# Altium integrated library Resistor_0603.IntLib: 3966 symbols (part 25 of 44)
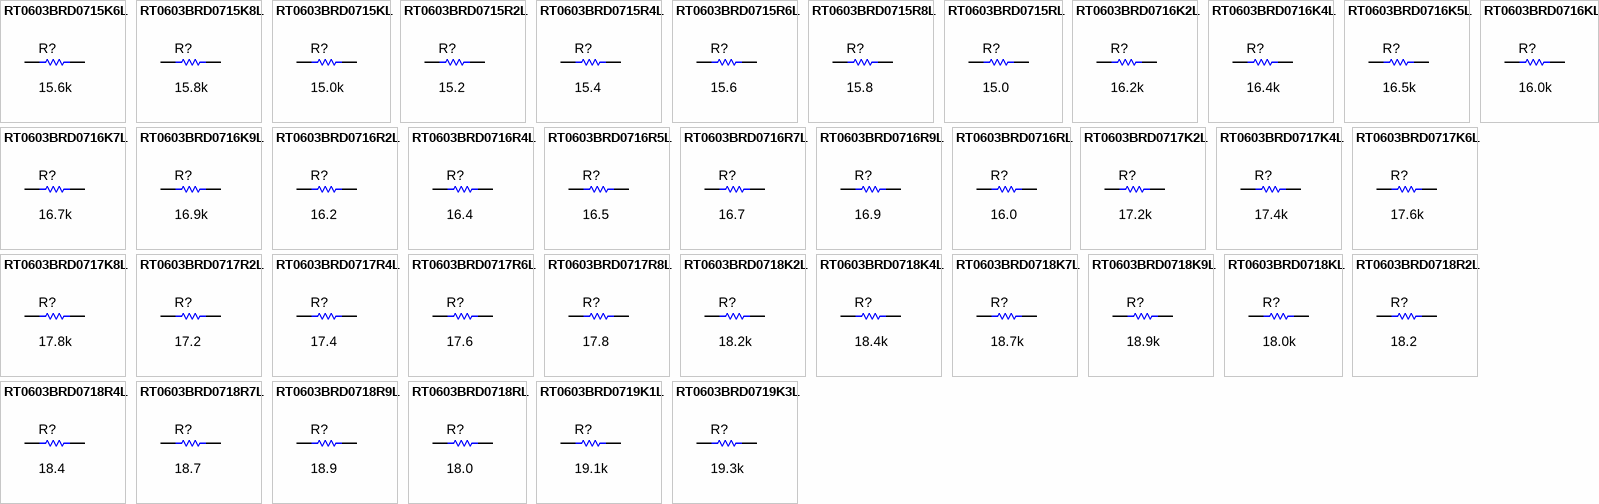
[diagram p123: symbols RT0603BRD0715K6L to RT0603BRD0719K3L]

## RT0603BRD0716KL
designator R?  ValueDisplayed: 16.0k  (hidden comment: RT0603BRD0716KL)
RES, 16.0 k, 0.1%, 0.1 W, 0603; Manufacturer: Yageo America; CompType: Resistor; Value: 16.0k; Res_ohm: 16000; Value_Code: 16k0; Tolerance_%: 0.1; Value2: 0.1W; VDC_V: 75; TempCo: 25 ppm/C; SizeArea_mm2: 1.28; SizeX_mm: 1.6; SizeY_mm: 0.8; SizeZ_mm: 1; EIA_Code: E192; U/M: EA; AEC Category: Q200
signal-integrity model Resistor
simulation model Resistor
footprint 0603
footprint 0603M
footprint 0603L
footprint 0603_HV
footprint 0603S
pins: 1, 2

## RT0603BRD0716R2L
designator R?  ValueDisplayed: 16.2  (hidden comment: RT0603BRD0716R2L)
RES, 16.2, 0.1%, 0.1 W, 0603; Manufacturer: Yageo America; CompType: Resistor; Value: 16.2; Value_Code: 16R2; Tolerance_%: 0.1; Value2: 0.1W; VDC_V: 75; TempCo: 25 ppm/C; SizeArea_mm2: 1.28; SizeX_mm: 1.6; SizeY_mm: 0.8; SizeZ_mm: 1; EIA_Code: E192; U/M: EA; AEC Category: Q200
signal-integrity model Resistor
simulation model Resistor
footprint 0603
footprint 0603M
footprint 0603L
footprint 0603_HV
footprint 0603S
pins: 1, 2

## RT0603BRD0716R4L
designator R?  ValueDisplayed: 16.4  (hidden comment: RT0603BRD0716R4L)
RES, 16.4, 0.1%, 0.1 W, 0603; Manufacturer: Yageo America; CompType: Resistor; Value: 16.4; Value_Code: 16R4; Tolerance_%: 0.1; Value2: 0.1W; VDC_V: 75; TempCo: 25 ppm/C; SizeArea_mm2: 1.28; SizeX_mm: 1.6; SizeY_mm: 0.8; SizeZ_mm: 1; EIA_Code: E192; U/M: EA; AEC Category: Q200
signal-integrity model Resistor
simulation model Resistor
footprint 0603
footprint 0603M
footprint 0603L
footprint 0603_HV
footprint 0603S
pins: 1, 2

## RT0603BRD0716R5L
designator R?  ValueDisplayed: 16.5  (hidden comment: RT0603BRD0716R5L)
RES, 16.5, 0.1%, 0.1 W, 0603; Manufacturer: Yageo America; CompType: Resistor; Value: 16.5; Value_Code: 16R5; Tolerance_%: 0.1; Value2: 0.1W; VDC_V: 75; TempCo: 25 ppm/C; SizeArea_mm2: 1.28; SizeX_mm: 1.6; SizeY_mm: 0.8; SizeZ_mm: 1; EIA_Code: E192; U/M: EA; AEC Category: Q200
signal-integrity model Resistor
simulation model Resistor
footprint 0603
footprint 0603M
footprint 0603L
footprint 0603_HV
footprint 0603S
pins: 1, 2

## RT0603BRD0716R7L
designator R?  ValueDisplayed: 16.7  (hidden comment: RT0603BRD0716R7L)
RES, 16.7, 0.1%, 0.1 W, 0603; Manufacturer: Yageo America; CompType: Resistor; Value: 16.7; Value_Code: 16R7; Tolerance_%: 0.1; Value2: 0.1W; VDC_V: 75; TempCo: 25 ppm/C; SizeArea_mm2: 1.28; SizeX_mm: 1.6; SizeY_mm: 0.8; SizeZ_mm: 1; EIA_Code: E192; U/M: EA; AEC Category: Q200
signal-integrity model Resistor
simulation model Resistor
footprint 0603
footprint 0603M
footprint 0603L
footprint 0603_HV
footprint 0603S
pins: 1, 2

## RT0603BRD0716R9L
designator R?  ValueDisplayed: 16.9  (hidden comment: RT0603BRD0716R9L)
RES, 16.9, 0.1%, 0.1 W, 0603; Manufacturer: Yageo America; CompType: Resistor; Value: 16.9; Value_Code: 16R9; Tolerance_%: 0.1; Value2: 0.1W; VDC_V: 75; TempCo: 25 ppm/C; SizeArea_mm2: 1.28; SizeX_mm: 1.6; SizeY_mm: 0.8; SizeZ_mm: 1; EIA_Code: E192; U/M: EA; AEC Category: Q200
signal-integrity model Resistor
simulation model Resistor
footprint 0603
footprint 0603M
footprint 0603L
footprint 0603_HV
footprint 0603S
pins: 1, 2

## RT0603BRD0716RL
designator R?  ValueDisplayed: 16.0  (hidden comment: RT0603BRD0716RL)
RES, 16.0, 0.1%, 0.1 W, 0603; Manufacturer: Yageo America; CompType: Resistor; Value: 16.0; Res_ohm: 16; Value_Code: 16R0; Tolerance_%: 0.1; Value2: 0.1W; VDC_V: 75; TempCo: 25 ppm/C; SizeArea_mm2: 1.28; SizeX_mm: 1.6; SizeY_mm: 0.8; SizeZ_mm: 1; EIA_Code: E192; U/M: EA; AEC Category: Q200
signal-integrity model Resistor
simulation model Resistor
footprint 0603
footprint 0603M
footprint 0603L
footprint 0603_HV
footprint 0603S
pins: 1, 2

## RT0603BRD0717K2L
designator R?  ValueDisplayed: 17.2k  (hidden comment: RT0603BRD0717K2L)
RES, 17.2 k, 0.1%, 0.1 W, 0603; Manufacturer: Yageo America; CompType: Resistor; Value: 17.2k; Res_ohm: 17200; Value_Code: 17k2; Tolerance_%: 0.1; Value2: 0.1W; VDC_V: 75; TempCo: 25 ppm/C; SizeArea_mm2: 1.28; SizeX_mm: 1.6; SizeY_mm: 0.8; SizeZ_mm: 1; EIA_Code: E192; U/M: EA; AEC Category: Q200
signal-integrity model Resistor
simulation model Resistor
footprint 0603
footprint 0603M
footprint 0603L
footprint 0603_HV
footprint 0603S
pins: 1, 2

## RT0603BRD0717K4L
designator R?  ValueDisplayed: 17.4k  (hidden comment: RT0603BRD0717K4L)
RES, 17.4 k, 0.1%, 0.1 W, 0603; Manufacturer: Yageo America; CompType: Resistor; Value: 17.4k; Res_ohm: 17400; Value_Code: 17k4; Tolerance_%: 0.1; Value2: 0.1W; VDC_V: 75; TempCo: 25 ppm/C; SizeArea_mm2: 1.28; SizeX_mm: 1.6; SizeY_mm: 0.8; SizeZ_mm: 1; EIA_Code: E192; U/M: EA; AEC Category: Q200
signal-integrity model Resistor
simulation model Resistor
footprint 0603
footprint 0603M
footprint 0603L
footprint 0603_HV
footprint 0603S
pins: 1, 2

## RT0603BRD0717K6L
designator R?  ValueDisplayed: 17.6k  (hidden comment: RT0603BRD0717K6L)
RES, 17.6 k, 0.1%, 0.1 W, 0603; Manufacturer: Yageo America; CompType: Resistor; Value: 17.6k; Res_ohm: 17600; Value_Code: 17k6; Tolerance_%: 0.1; Value2: 0.1W; VDC_V: 75; TempCo: 25 ppm/C; SizeArea_mm2: 1.28; SizeX_mm: 1.6; SizeY_mm: 0.8; SizeZ_mm: 1; EIA_Code: E192; U/M: EA; AEC Category: Q200
signal-integrity model Resistor
simulation model Resistor
footprint 0603
footprint 0603M
footprint 0603L
footprint 0603_HV
footprint 0603S
pins: 1, 2

## RT0603BRD0717K8L
designator R?  ValueDisplayed: 17.8k  (hidden comment: RT0603BRD0717K8L)
RES, 17.8 k, 0.1%, 0.1 W, 0603; Manufacturer: Yageo America; CompType: Resistor; Value: 17.8k; Res_ohm: 17800; Value_Code: 17k8; Tolerance_%: 0.1; Value2: 0.1W; VDC_V: 75; TempCo: 25 ppm/C; SizeArea_mm2: 1.28; SizeX_mm: 1.6; SizeY_mm: 0.8; SizeZ_mm: 1; EIA_Code: E192; U/M: EA; AEC Category: Q200
signal-integrity model Resistor
simulation model Resistor
footprint 0603
footprint 0603M
footprint 0603L
footprint 0603_HV
footprint 0603S
pins: 1, 2

## RT0603BRD0717R2L
designator R?  ValueDisplayed: 17.2  (hidden comment: RT0603BRD0717R2L)
RES, 17.2, 0.1%, 0.1 W, 0603; Manufacturer: Yageo America; CompType: Resistor; Value: 17.2; Value_Code: 17R2; Tolerance_%: 0.1; Value2: 0.1W; VDC_V: 75; TempCo: 25 ppm/C; SizeArea_mm2: 1.28; SizeX_mm: 1.6; SizeY_mm: 0.8; SizeZ_mm: 1; EIA_Code: E192; U/M: EA; AEC Category: Q200
signal-integrity model Resistor
simulation model Resistor
footprint 0603
footprint 0603M
footprint 0603L
footprint 0603_HV
footprint 0603S
pins: 1, 2

## RT0603BRD0717R4L
designator R?  ValueDisplayed: 17.4  (hidden comment: RT0603BRD0717R4L)
RES, 17.4, 0.1%, 0.1 W, 0603; Manufacturer: Yageo America; CompType: Resistor; Value: 17.4; Value_Code: 17R4; Tolerance_%: 0.1; Value2: 0.1W; VDC_V: 75; TempCo: 25 ppm/C; SizeArea_mm2: 1.28; SizeX_mm: 1.6; SizeY_mm: 0.8; SizeZ_mm: 1; EIA_Code: E192; U/M: EA; AEC Category: Q200
signal-integrity model Resistor
simulation model Resistor
footprint 0603
footprint 0603M
footprint 0603L
footprint 0603_HV
footprint 0603S
pins: 1, 2

## RT0603BRD0717R6L
designator R?  ValueDisplayed: 17.6  (hidden comment: RT0603BRD0717R6L)
RES, 17.6, 0.1%, 0.1 W, 0603; Manufacturer: Yageo America; CompType: Resistor; Value: 17.6; Value_Code: 17R6; Tolerance_%: 0.1; Value2: 0.1W; VDC_V: 75; TempCo: 25 ppm/C; SizeArea_mm2: 1.28; SizeX_mm: 1.6; SizeY_mm: 0.8; SizeZ_mm: 1; EIA_Code: E192; U/M: EA; AEC Category: Q200
signal-integrity model Resistor
simulation model Resistor
footprint 0603
footprint 0603M
footprint 0603L
footprint 0603_HV
footprint 0603S
pins: 1, 2

## RT0603BRD0717R8L
designator R?  ValueDisplayed: 17.8  (hidden comment: RT0603BRD0717R8L)
RES, 17.8, 0.1%, 0.1 W, 0603; Manufacturer: Yageo America; CompType: Resistor; Value: 17.8; Value_Code: 17R8; Tolerance_%: 0.1; Value2: 0.1W; VDC_V: 75; TempCo: 25 ppm/C; SizeArea_mm2: 1.28; SizeX_mm: 1.6; SizeY_mm: 0.8; SizeZ_mm: 1; EIA_Code: E192; U/M: EA; AEC Category: Q200
signal-integrity model Resistor
simulation model Resistor
footprint 0603
footprint 0603M
footprint 0603L
footprint 0603_HV
footprint 0603S
pins: 1, 2

## RT0603BRD0718K2L
designator R?  ValueDisplayed: 18.2k  (hidden comment: RT0603BRD0718K2L)
RES, 18.2 k, 0.1%, 0.1 W, 0603; Manufacturer: Yageo America; CompType: Resistor; Value: 18.2k; Res_ohm: 18200; Value_Code: 18k2; Tolerance_%: 0.1; Value2: 0.1W; VDC_V: 75; TempCo: 25 ppm/C; SizeArea_mm2: 1.28; SizeX_mm: 1.6; SizeY_mm: 0.8; SizeZ_mm: 1; EIA_Code: E192; U/M: EA; AEC Category: Q200
signal-integrity model Resistor
simulation model Resistor
footprint 0603
footprint 0603M
footprint 0603L
footprint 0603_HV
footprint 0603S
pins: 1, 2

## RT0603BRD0718K4L
designator R?  ValueDisplayed: 18.4k  (hidden comment: RT0603BRD0718K4L)
RES, 18.4 k, 0.1%, 0.1 W, 0603; Manufacturer: Yageo America; CompType: Resistor; Value: 18.4k; Res_ohm: 18400; Value_Code: 18k4; Tolerance_%: 0.1; Value2: 0.1W; VDC_V: 75; TempCo: 25 ppm/C; SizeArea_mm2: 1.28; SizeX_mm: 1.6; SizeY_mm: 0.8; SizeZ_mm: 1; EIA_Code: E192; U/M: EA; AEC Category: Q200
signal-integrity model Resistor
simulation model Resistor
footprint 0603
footprint 0603M
footprint 0603L
footprint 0603_HV
footprint 0603S
pins: 1, 2

## RT0603BRD0718K7L
designator R?  ValueDisplayed: 18.7k  (hidden comment: RT0603BRD0718K7L)
RES, 18.7 k, 0.1%, 0.1 W, 0603; Manufacturer: Yageo America; CompType: Resistor; Value: 18.7k; Res_ohm: 18700; Value_Code: 18k7; Tolerance_%: 0.1; Value2: 0.1W; VDC_V: 75; TempCo: 25 ppm/C; SizeArea_mm2: 1.28; SizeX_mm: 1.6; SizeY_mm: 0.8; SizeZ_mm: 1; EIA_Code: E192; U/M: EA; AEC Category: Q200
signal-integrity model Resistor
simulation model Resistor
footprint 0603
footprint 0603M
footprint 0603L
footprint 0603_HV
footprint 0603S
pins: 1, 2

## RT0603BRD0718K9L
designator R?  ValueDisplayed: 18.9k  (hidden comment: RT0603BRD0718K9L)
RES, 18.9 k, 0.1%, 0.1 W, 0603; Manufacturer: Yageo America; CompType: Resistor; Value: 18.9k; Res_ohm: 18900; Value_Code: 18k9; Tolerance_%: 0.1; Value2: 0.1W; VDC_V: 75; TempCo: 25 ppm/C; SizeArea_mm2: 1.28; SizeX_mm: 1.6; SizeY_mm: 0.8; SizeZ_mm: 1; EIA_Code: E192; U/M: EA; AEC Category: Q200
signal-integrity model Resistor
simulation model Resistor
footprint 0603
footprint 0603M
footprint 0603L
footprint 0603_HV
footprint 0603S
pins: 1, 2

## RT0603BRD0718KL
designator R?  ValueDisplayed: 18.0k  (hidden comment: RT0603BRD0718KL)
RES, 18.0 k, 0.1%, 0.1 W, 0603; Manufacturer: Yageo America; CompType: Resistor; Value: 18.0k; Res_ohm: 18000; Value_Code: 18k0; Tolerance_%: 0.1; Value2: 0.1W; VDC_V: 75; TempCo: 25 ppm/C; SizeArea_mm2: 1.28; SizeX_mm: 1.6; SizeY_mm: 0.8; SizeZ_mm: 1; EIA_Code: E192; U/M: EA; AEC Category: Q200
signal-integrity model Resistor
simulation model Resistor
footprint 0603
footprint 0603M
footprint 0603L
footprint 0603_HV
footprint 0603S
pins: 1, 2

## RT0603BRD0718R2L
designator R?  ValueDisplayed: 18.2  (hidden comment: RT0603BRD0718R2L)
RES, 18.2, 0.1%, 0.1 W, 0603; Manufacturer: Yageo America; CompType: Resistor; Value: 18.2; Value_Code: 18R2; Tolerance_%: 0.1; Value2: 0.1W; VDC_V: 75; TempCo: 25 ppm/C; SizeArea_mm2: 1.28; SizeX_mm: 1.6; SizeY_mm: 0.8; SizeZ_mm: 1; EIA_Code: E192; U/M: EA; AEC Category: Q200
signal-integrity model Resistor
simulation model Resistor
footprint 0603
footprint 0603M
footprint 0603L
footprint 0603_HV
footprint 0603S
pins: 1, 2

## RT0603BRD0718R4L
designator R?  ValueDisplayed: 18.4  (hidden comment: RT0603BRD0718R4L)
RES, 18.4, 0.1%, 0.1 W, 0603; Manufacturer: Yageo America; CompType: Resistor; Value: 18.4; Value_Code: 18R4; Tolerance_%: 0.1; Value2: 0.1W; VDC_V: 75; TempCo: 25 ppm/C; SizeArea_mm2: 1.28; SizeX_mm: 1.6; SizeY_mm: 0.8; SizeZ_mm: 1; EIA_Code: E192; U/M: EA; AEC Category: Q200
signal-integrity model Resistor
simulation model Resistor
footprint 0603
footprint 0603M
footprint 0603L
footprint 0603_HV
footprint 0603S
pins: 1, 2

## RT0603BRD0718R7L
designator R?  ValueDisplayed: 18.7  (hidden comment: RT0603BRD0718R7L)
RES, 18.7, 0.1%, 0.1 W, 0603; Manufacturer: Yageo America; CompType: Resistor; Value: 18.7; Value_Code: 18R7; Tolerance_%: 0.1; Value2: 0.1W; VDC_V: 75; TempCo: 25 ppm/C; SizeArea_mm2: 1.28; SizeX_mm: 1.6; SizeY_mm: 0.8; SizeZ_mm: 1; EIA_Code: E192; U/M: EA; AEC Category: Q200
signal-integrity model Resistor
simulation model Resistor
footprint 0603
footprint 0603M
footprint 0603L
footprint 0603_HV
footprint 0603S
pins: 1, 2

## RT0603BRD0718R9L
designator R?  ValueDisplayed: 18.9  (hidden comment: RT0603BRD0718R9L)
RES, 18.9, 0.1%, 0.1 W, 0603; Manufacturer: Yageo America; CompType: Resistor; Value: 18.9; Value_Code: 18R9; Tolerance_%: 0.1; Value2: 0.1W; VDC_V: 75; TempCo: 25 ppm/C; SizeArea_mm2: 1.28; SizeX_mm: 1.6; SizeY_mm: 0.8; SizeZ_mm: 1; EIA_Code: E192; U/M: EA; AEC Category: Q200
signal-integrity model Resistor
simulation model Resistor
footprint 0603
footprint 0603M
footprint 0603L
footprint 0603_HV
footprint 0603S
pins: 1, 2

## RT0603BRD0718RL
designator R?  ValueDisplayed: 18.0  (hidden comment: RT0603BRD0718RL)
RES, 18.0, 0.1%, 0.1 W, 0603; Manufacturer: Yageo America; CompType: Resistor; Value: 18.0; Res_ohm: 18; Value_Code: 18R0; Tolerance_%: 0.1; Value2: 0.1W; VDC_V: 75; TempCo: 25 ppm/C; SizeArea_mm2: 1.28; SizeX_mm: 1.6; SizeY_mm: 0.8; SizeZ_mm: 1; EIA_Code: E192; U/M: EA; AEC Category: Q200
signal-integrity model Resistor
simulation model Resistor
footprint 0603
footprint 0603M
footprint 0603L
footprint 0603_HV
footprint 0603S
pins: 1, 2

## RT0603BRD0719K1L
designator R?  ValueDisplayed: 19.1k  (hidden comment: RT0603BRD0719K1L)
RES, 19.1 k, 0.1%, 0.1 W, 0603; Manufacturer: Yageo America; CompType: Resistor; Value: 19.1k; Res_ohm: 19100; Value_Code: 19k1; Tolerance_%: 0.1; Value2: 0.1W; VDC_V: 75; TempCo: 25 ppm/C; SizeArea_mm2: 1.28; SizeX_mm: 1.6; SizeY_mm: 0.8; SizeZ_mm: 1; EIA_Code: E192; U/M: EA; AEC Category: Q200
signal-integrity model Resistor
simulation model Resistor
footprint 0603
footprint 0603M
footprint 0603L
footprint 0603_HV
footprint 0603S
pins: 1, 2

## RT0603BRD0719K3L
designator R?  ValueDisplayed: 19.3k  (hidden comment: RT0603BRD0719K3L)
RES, 19.3 k, 0.1%, 0.1 W, 0603; Manufacturer: Yageo America; CompType: Resistor; Value: 19.3k; Res_ohm: 19300; Value_Code: 19k3; Tolerance_%: 0.1; Value2: 0.1W; VDC_V: 75; TempCo: 25 ppm/C; SizeArea_mm2: 1.28; SizeX_mm: 1.6; SizeY_mm: 0.8; SizeZ_mm: 1; EIA_Code: E192; U/M: EA; AEC Category: Q200
signal-integrity model Resistor
simulation model Resistor
footprint 0603
footprint 0603M
footprint 0603L
footprint 0603_HV
footprint 0603S
pins: 1, 2

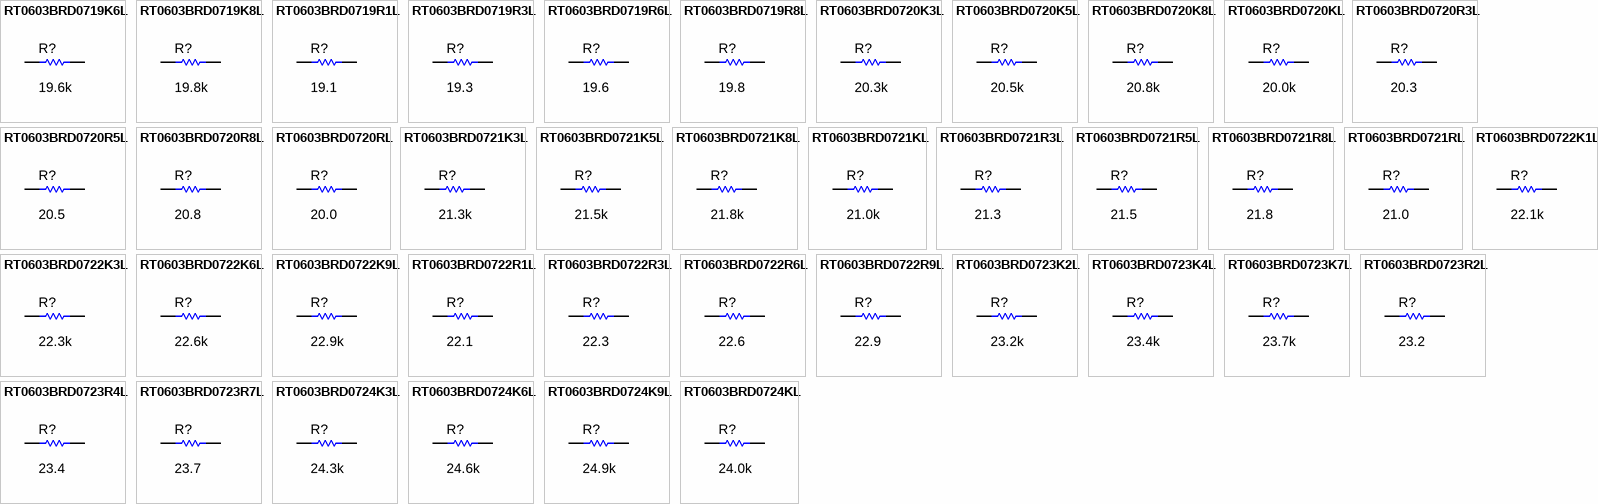
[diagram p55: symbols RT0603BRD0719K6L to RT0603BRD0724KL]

## RT0603BRD0719K6L
designator R?  ValueDisplayed: 19.6k  (hidden comment: RT0603BRD0719K6L)
RES, 19.6 k, 0.1%, 0.1 W, 0603; Manufacturer: Yageo America; CompType: Resistor; Value: 19.6k; Res_ohm: 19600; Value_Code: 19k6; Tolerance_%: 0.1; Value2: 0.1W; VDC_V: 75; TempCo: 25 ppm/C; SizeArea_mm2: 1.28; SizeX_mm: 1.6; SizeY_mm: 0.8; SizeZ_mm: 1; EIA_Code: E192; U/M: EA; AEC Category: Q200
signal-integrity model Resistor
simulation model Resistor
footprint 0603
footprint 0603M
footprint 0603L
footprint 0603_HV
footprint 0603S
pins: 1, 2

## RT0603BRD0719K8L
designator R?  ValueDisplayed: 19.8k  (hidden comment: RT0603BRD0719K8L)
RES, 19.8 k, 0.1%, 0.1 W, 0603; Manufacturer: Yageo America; CompType: Resistor; Value: 19.8k; Res_ohm: 19800; Value_Code: 19k8; Tolerance_%: 0.1; Value2: 0.1W; VDC_V: 75; TempCo: 25 ppm/C; SizeArea_mm2: 1.28; SizeX_mm: 1.6; SizeY_mm: 0.8; SizeZ_mm: 1; EIA_Code: E192; U/M: EA; AEC Category: Q200
signal-integrity model Resistor
simulation model Resistor
footprint 0603
footprint 0603M
footprint 0603L
footprint 0603_HV
footprint 0603S
pins: 1, 2

## RT0603BRD0719R1L
designator R?  ValueDisplayed: 19.1  (hidden comment: RT0603BRD0719R1L)
RES, 19.1, 0.1%, 0.1 W, 0603; Manufacturer: Yageo America; CompType: Resistor; Value: 19.1; Value_Code: 19R1; Tolerance_%: 0.1; Value2: 0.1W; VDC_V: 75; TempCo: 25 ppm/C; SizeArea_mm2: 1.28; SizeX_mm: 1.6; SizeY_mm: 0.8; SizeZ_mm: 1; EIA_Code: E192; U/M: EA; AEC Category: Q200
signal-integrity model Resistor
simulation model Resistor
footprint 0603
footprint 0603M
footprint 0603L
footprint 0603_HV
footprint 0603S
pins: 1, 2

## RT0603BRD0719R3L
designator R?  ValueDisplayed: 19.3  (hidden comment: RT0603BRD0719R3L)
RES, 19.3, 0.1%, 0.1 W, 0603; Manufacturer: Yageo America; CompType: Resistor; Value: 19.3; Value_Code: 19R3; Tolerance_%: 0.1; Value2: 0.1W; VDC_V: 75; TempCo: 25 ppm/C; SizeArea_mm2: 1.28; SizeX_mm: 1.6; SizeY_mm: 0.8; SizeZ_mm: 1; EIA_Code: E192; U/M: EA; AEC Category: Q200
signal-integrity model Resistor
simulation model Resistor
footprint 0603
footprint 0603M
footprint 0603L
footprint 0603_HV
footprint 0603S
pins: 1, 2

## RT0603BRD0719R6L
designator R?  ValueDisplayed: 19.6  (hidden comment: RT0603BRD0719R6L)
RES, 19.6, 0.1%, 0.1 W, 0603; Manufacturer: Yageo America; CompType: Resistor; Value: 19.6; Value_Code: 19R6; Tolerance_%: 0.1; Value2: 0.1W; VDC_V: 75; TempCo: 25 ppm/C; SizeArea_mm2: 1.28; SizeX_mm: 1.6; SizeY_mm: 0.8; SizeZ_mm: 1; EIA_Code: E192; U/M: EA; AEC Category: Q200
signal-integrity model Resistor
simulation model Resistor
footprint 0603
footprint 0603M
footprint 0603L
footprint 0603_HV
footprint 0603S
pins: 1, 2

## RT0603BRD0719R8L
designator R?  ValueDisplayed: 19.8  (hidden comment: RT0603BRD0719R8L)
RES, 19.8, 0.1%, 0.1 W, 0603; Manufacturer: Yageo America; CompType: Resistor; Value: 19.8; Value_Code: 19R8; Tolerance_%: 0.1; Value2: 0.1W; VDC_V: 75; TempCo: 25 ppm/C; SizeArea_mm2: 1.28; SizeX_mm: 1.6; SizeY_mm: 0.8; SizeZ_mm: 1; EIA_Code: E192; U/M: EA; AEC Category: Q200
signal-integrity model Resistor
simulation model Resistor
footprint 0603
footprint 0603M
footprint 0603L
footprint 0603_HV
footprint 0603S
pins: 1, 2

## RT0603BRD0720K3L
designator R?  ValueDisplayed: 20.3k  (hidden comment: RT0603BRD0720K3L)
RES, 20.3 k, 0.1%, 0.1 W, 0603; Manufacturer: Yageo America; CompType: Resistor; Value: 20.3k; Res_ohm: 20300; Value_Code: 20k3; Tolerance_%: 0.1; Value2: 0.1W; VDC_V: 75; TempCo: 25 ppm/C; SizeArea_mm2: 1.28; SizeX_mm: 1.6; SizeY_mm: 0.8; SizeZ_mm: 1; EIA_Code: E192; U/M: EA; AEC Category: Q200
signal-integrity model Resistor
simulation model Resistor
footprint 0603
footprint 0603M
footprint 0603L
footprint 0603_HV
footprint 0603S
pins: 1, 2

## RT0603BRD0720K5L
designator R?  ValueDisplayed: 20.5k  (hidden comment: RT0603BRD0720K5L)
RES, 20.5 k, 0.1%, 0.1 W, 0603; Manufacturer: Yageo America; CompType: Resistor; Value: 20.5k; Res_ohm: 20500; Value_Code: 20k5; Tolerance_%: 0.1; Value2: 0.1W; VDC_V: 75; TempCo: 25 ppm/C; SizeArea_mm2: 1.28; SizeX_mm: 1.6; SizeY_mm: 0.8; SizeZ_mm: 1; EIA_Code: E192; U/M: EA; AEC Category: Q200
signal-integrity model Resistor
simulation model Resistor
footprint 0603
footprint 0603M
footprint 0603L
footprint 0603_HV
footprint 0603S
pins: 1, 2

## RT0603BRD0720K8L
designator R?  ValueDisplayed: 20.8k  (hidden comment: RT0603BRD0720K8L)
RES, 20.8 k, 0.1%, 0.1 W, 0603; Manufacturer: Yageo America; CompType: Resistor; Value: 20.8k; Res_ohm: 20800; Value_Code: 20k8; Tolerance_%: 0.1; Value2: 0.1W; VDC_V: 75; TempCo: 25 ppm/C; SizeArea_mm2: 1.28; SizeX_mm: 1.6; SizeY_mm: 0.8; SizeZ_mm: 1; EIA_Code: E192; U/M: EA; AEC Category: Q200
signal-integrity model Resistor
simulation model Resistor
footprint 0603
footprint 0603M
footprint 0603L
footprint 0603_HV
footprint 0603S
pins: 1, 2

## RT0603BRD0720KL
designator R?  ValueDisplayed: 20.0k  (hidden comment: RT0603BRD0720KL)
RES, 20.0 k, 0.1%, 0.1 W, 0603; Manufacturer: Yageo America; CompType: Resistor; Value: 20.0k; Res_ohm: 20000; Value_Code: 20k0; Tolerance_%: 0.1; Value2: 0.1W; VDC_V: 75; TempCo: 25 ppm/C; SizeArea_mm2: 1.28; SizeX_mm: 1.6; SizeY_mm: 0.8; SizeZ_mm: 1; EIA_Code: E192; U/M: EA; AEC Category: Q200; Green_Lifecycle: Active; Green_REACh: Passed
signal-integrity model Resistor
simulation model Resistor
footprint 0603
footprint 0603M
footprint 0603L
footprint 0603_HV
footprint 0603S
pins: 1, 2

## RT0603BRD0720R3L
designator R?  ValueDisplayed: 20.3  (hidden comment: RT0603BRD0720R3L)
RES, 20.3, 0.1%, 0.1 W, 0603; Manufacturer: Yageo America; CompType: Resistor; Value: 20.3; Value_Code: 20R3; Tolerance_%: 0.1; Value2: 0.1W; VDC_V: 75; TempCo: 25 ppm/C; SizeArea_mm2: 1.28; SizeX_mm: 1.6; SizeY_mm: 0.8; SizeZ_mm: 1; EIA_Code: E192; U/M: EA; AEC Category: Q200
signal-integrity model Resistor
simulation model Resistor
footprint 0603
footprint 0603M
footprint 0603L
footprint 0603_HV
footprint 0603S
pins: 1, 2

## RT0603BRD0720R5L
designator R?  ValueDisplayed: 20.5  (hidden comment: RT0603BRD0720R5L)
RES, 20.5, 0.1%, 0.1 W, 0603; Manufacturer: Yageo America; CompType: Resistor; Value: 20.5; Value_Code: 20R5; Tolerance_%: 0.1; Value2: 0.1W; VDC_V: 75; TempCo: 25 ppm/C; SizeArea_mm2: 1.28; SizeX_mm: 1.6; SizeY_mm: 0.8; SizeZ_mm: 1; EIA_Code: E192; U/M: EA; AEC Category: Q200
signal-integrity model Resistor
simulation model Resistor
footprint 0603
footprint 0603M
footprint 0603L
footprint 0603_HV
footprint 0603S
pins: 1, 2

## RT0603BRD0720R8L
designator R?  ValueDisplayed: 20.8  (hidden comment: RT0603BRD0720R8L)
RES, 20.8, 0.1%, 0.1 W, 0603; Manufacturer: Yageo America; CompType: Resistor; Value: 20.8; Value_Code: 20R8; Tolerance_%: 0.1; Value2: 0.1W; VDC_V: 75; TempCo: 25 ppm/C; SizeArea_mm2: 1.28; SizeX_mm: 1.6; SizeY_mm: 0.8; SizeZ_mm: 1; EIA_Code: E192; U/M: EA; AEC Category: Q200
signal-integrity model Resistor
simulation model Resistor
footprint 0603
footprint 0603M
footprint 0603L
footprint 0603_HV
footprint 0603S
pins: 1, 2

## RT0603BRD0720RL
designator R?  ValueDisplayed: 20.0  (hidden comment: RT0603BRD0720RL)
RES, 20.0, 0.1%, 0.1 W, 0603; Manufacturer: Yageo America; CompType: Resistor; Value: 20.0; Res_ohm: 20; Value_Code: 20R0; Tolerance_%: 0.1; Value2: 0.1W; VDC_V: 75; TempCo: 25 ppm/C; SizeArea_mm2: 1.28; SizeX_mm: 1.6; SizeY_mm: 0.8; SizeZ_mm: 1; EIA_Code: E192; U/M: EA; AEC Category: Q200; Green_Lifecycle: Active; Green_REACh: Passed
signal-integrity model Resistor
simulation model Resistor
footprint 0603
footprint 0603M
footprint 0603L
footprint 0603_HV
footprint 0603S
pins: 1, 2

## RT0603BRD0721K3L
designator R?  ValueDisplayed: 21.3k  (hidden comment: RT0603BRD0721K3L)
RES, 21.3 k, 0.1%, 0.1 W, 0603; Manufacturer: Yageo America; CompType: Resistor; Value: 21.3k; Res_ohm: 21300; Value_Code: 21k3; Tolerance_%: 0.1; Value2: 0.1W; VDC_V: 75; TempCo: 25 ppm/C; SizeArea_mm2: 1.28; SizeX_mm: 1.6; SizeY_mm: 0.8; SizeZ_mm: 1; EIA_Code: E192; U/M: EA; AEC Category: Q200
signal-integrity model Resistor
simulation model Resistor
footprint 0603
footprint 0603M
footprint 0603L
footprint 0603_HV
footprint 0603S
pins: 1, 2

## RT0603BRD0721K5L
designator R?  ValueDisplayed: 21.5k  (hidden comment: RT0603BRD0721K5L)
RES, 21.5 k, 0.1%, 0.1 W, 0603; Manufacturer: Yageo America; CompType: Resistor; Value: 21.5k; Res_ohm: 21500; Value_Code: 21k5; Tolerance_%: 0.1; Value2: 0.1W; VDC_V: 75; TempCo: 25 ppm/C; SizeArea_mm2: 1.28; SizeX_mm: 1.6; SizeY_mm: 0.8; SizeZ_mm: 1; EIA_Code: E192; U/M: EA; AEC Category: Q200
signal-integrity model Resistor
simulation model Resistor
footprint 0603
footprint 0603M
footprint 0603L
footprint 0603_HV
footprint 0603S
pins: 1, 2

## RT0603BRD0721K8L
designator R?  ValueDisplayed: 21.8k  (hidden comment: RT0603BRD0721K8L)
RES, 21.8 k, 0.1%, 0.1 W, 0603; Manufacturer: Yageo America; CompType: Resistor; Value: 21.8k; Res_ohm: 21800; Value_Code: 21k8; Tolerance_%: 0.1; Value2: 0.1W; VDC_V: 75; TempCo: 25 ppm/C; SizeArea_mm2: 1.28; SizeX_mm: 1.6; SizeY_mm: 0.8; SizeZ_mm: 1; EIA_Code: E192; U/M: EA; AEC Category: Q200
signal-integrity model Resistor
simulation model Resistor
footprint 0603
footprint 0603M
footprint 0603L
footprint 0603_HV
footprint 0603S
pins: 1, 2

## RT0603BRD0721KL
designator R?  ValueDisplayed: 21.0k  (hidden comment: RT0603BRD0721KL)
RES, 21.0 k, 0.1%, 0.1 W, 0603; Manufacturer: Yageo America; CompType: Resistor; Value: 21.0k; Res_ohm: 21000; Value_Code: 21k0; Tolerance_%: 0.1; Value2: 0.1W; VDC_V: 75; TempCo: 25 ppm/C; SizeArea_mm2: 1.28; SizeX_mm: 1.6; SizeY_mm: 0.8; SizeZ_mm: 1; EIA_Code: E192; U/M: EA; AEC Category: Q200
signal-integrity model Resistor
simulation model Resistor
footprint 0603
footprint 0603M
footprint 0603L
footprint 0603_HV
footprint 0603S
pins: 1, 2

## RT0603BRD0721R3L
designator R?  ValueDisplayed: 21.3  (hidden comment: RT0603BRD0721R3L)
RES, 21.3, 0.1%, 0.1 W, 0603; Manufacturer: Yageo America; CompType: Resistor; Value: 21.3; Value_Code: 21R3; Tolerance_%: 0.1; Value2: 0.1W; VDC_V: 75; TempCo: 25 ppm/C; SizeArea_mm2: 1.28; SizeX_mm: 1.6; SizeY_mm: 0.8; SizeZ_mm: 1; EIA_Code: E192; U/M: EA; AEC Category: Q200
signal-integrity model Resistor
simulation model Resistor
footprint 0603
footprint 0603M
footprint 0603L
footprint 0603_HV
footprint 0603S
pins: 1, 2

## RT0603BRD0721R5L
designator R?  ValueDisplayed: 21.5  (hidden comment: RT0603BRD0721R5L)
RES, 21.5, 0.1%, 0.1 W, 0603; Manufacturer: Yageo America; CompType: Resistor; Value: 21.5; Value_Code: 21R5; Tolerance_%: 0.1; Value2: 0.1W; VDC_V: 75; TempCo: 25 ppm/C; SizeArea_mm2: 1.28; SizeX_mm: 1.6; SizeY_mm: 0.8; SizeZ_mm: 1; EIA_Code: E192; U/M: EA; AEC Category: Q200
signal-integrity model Resistor
simulation model Resistor
footprint 0603
footprint 0603M
footprint 0603L
footprint 0603_HV
footprint 0603S
pins: 1, 2

## RT0603BRD0721R8L
designator R?  ValueDisplayed: 21.8  (hidden comment: RT0603BRD0721R8L)
RES, 21.8, 0.1%, 0.1 W, 0603; Manufacturer: Yageo America; CompType: Resistor; Value: 21.8; Value_Code: 21R8; Tolerance_%: 0.1; Value2: 0.1W; VDC_V: 75; TempCo: 25 ppm/C; SizeArea_mm2: 1.28; SizeX_mm: 1.6; SizeY_mm: 0.8; SizeZ_mm: 1; EIA_Code: E192; U/M: EA; AEC Category: Q200
signal-integrity model Resistor
simulation model Resistor
footprint 0603
footprint 0603M
footprint 0603L
footprint 0603_HV
footprint 0603S
pins: 1, 2

## RT0603BRD0721RL
designator R?  ValueDisplayed: 21.0  (hidden comment: RT0603BRD0721RL)
RES, 21.0, 0.1%, 0.1 W, 0603; Manufacturer: Yageo America; CompType: Resistor; Value: 21.0; Res_ohm: 21; Value_Code: 21R0; Tolerance_%: 0.1; Value2: 0.1W; VDC_V: 75; TempCo: 25 ppm/C; SizeArea_mm2: 1.28; SizeX_mm: 1.6; SizeY_mm: 0.8; SizeZ_mm: 1; EIA_Code: E192; U/M: EA; AEC Category: Q200
signal-integrity model Resistor
simulation model Resistor
footprint 0603
footprint 0603M
footprint 0603L
footprint 0603_HV
footprint 0603S
pins: 1, 2

## RT0603BRD0722K1L
designator R?  ValueDisplayed: 22.1k  (hidden comment: RT0603BRD0722K1L)
RES, 22.1 k, 0.1%, 0.1 W, 0603; Manufacturer: Yageo America; CompType: Resistor; Value: 22.1k; Res_ohm: 22100; Value_Code: 22k1; Tolerance_%: 0.1; Value2: 0.1W; VDC_V: 75; TempCo: 25 ppm/C; SizeArea_mm2: 1.28; SizeX_mm: 1.6; SizeY_mm: 0.8; SizeZ_mm: 1; EIA_Code: E192; U/M: EA; AEC Category: Q200
signal-integrity model Resistor
simulation model Resistor
footprint 0603
footprint 0603M
footprint 0603L
footprint 0603_HV
footprint 0603S
pins: 1, 2

## RT0603BRD0722K3L
designator R?  ValueDisplayed: 22.3k  (hidden comment: RT0603BRD0722K3L)
RES, 22.3 k, 0.1%, 0.1 W, 0603; Manufacturer: Yageo America; CompType: Resistor; Value: 22.3k; Res_ohm: 22300; Value_Code: 22k3; Tolerance_%: 0.1; Value2: 0.1W; VDC_V: 75; TempCo: 25 ppm/C; SizeArea_mm2: 1.28; SizeX_mm: 1.6; SizeY_mm: 0.8; SizeZ_mm: 1; EIA_Code: E192; U/M: EA; AEC Category: Q200
signal-integrity model Resistor
simulation model Resistor
footprint 0603
footprint 0603M
footprint 0603L
footprint 0603_HV
footprint 0603S
pins: 1, 2

## RT0603BRD0722K6L
designator R?  ValueDisplayed: 22.6k  (hidden comment: RT0603BRD0722K6L)
RES, 22.6 k, 0.1%, 0.1 W, 0603; Manufacturer: Yageo America; CompType: Resistor; Value: 22.6k; Res_ohm: 22600; Value_Code: 22k6; Tolerance_%: 0.1; Value2: 0.1W; VDC_V: 75; TempCo: 25 ppm/C; SizeArea_mm2: 1.28; SizeX_mm: 1.6; SizeY_mm: 0.8; SizeZ_mm: 1; EIA_Code: E192; U/M: EA; AEC Category: Q200; Green_Lifecycle: Active; Green_REACh: Passed
signal-integrity model Resistor
simulation model Resistor
footprint 0603
footprint 0603M
footprint 0603L
footprint 0603_HV
footprint 0603S
pins: 1, 2

## RT0603BRD0722K9L
designator R?  ValueDisplayed: 22.9k  (hidden comment: RT0603BRD0722K9L)
RES, 22.9 k, 0.1%, 0.1 W, 0603; Manufacturer: Yageo America; CompType: Resistor; Value: 22.9k; Res_ohm: 22900; Value_Code: 22k9; Tolerance_%: 0.1; Value2: 0.1W; VDC_V: 75; TempCo: 25 ppm/C; SizeArea_mm2: 1.28; SizeX_mm: 1.6; SizeY_mm: 0.8; SizeZ_mm: 1; EIA_Code: E192; U/M: EA; AEC Category: Q200
signal-integrity model Resistor
simulation model Resistor
footprint 0603
footprint 0603M
footprint 0603L
footprint 0603_HV
footprint 0603S
pins: 1, 2

## RT0603BRD0722R1L
designator R?  ValueDisplayed: 22.1  (hidden comment: RT0603BRD0722R1L)
RES, 22.1, 0.1%, 0.1 W, 0603; Manufacturer: Yageo America; CompType: Resistor; Value: 22.1; Value_Code: 22R1; Tolerance_%: 0.1; Value2: 0.1W; VDC_V: 75; TempCo: 25 ppm/C; SizeArea_mm2: 1.28; SizeX_mm: 1.6; SizeY_mm: 0.8; SizeZ_mm: 1; EIA_Code: E192; U/M: EA; AEC Category: Q200
signal-integrity model Resistor
simulation model Resistor
footprint 0603
footprint 0603M
footprint 0603L
footprint 0603_HV
footprint 0603S
pins: 1, 2

## RT0603BRD0722R3L
designator R?  ValueDisplayed: 22.3  (hidden comment: RT0603BRD0722R3L)
RES, 22.3, 0.1%, 0.1 W, 0603; Manufacturer: Yageo America; CompType: Resistor; Value: 22.3; Value_Code: 22R3; Tolerance_%: 0.1; Value2: 0.1W; VDC_V: 75; TempCo: 25 ppm/C; SizeArea_mm2: 1.28; SizeX_mm: 1.6; SizeY_mm: 0.8; SizeZ_mm: 1; EIA_Code: E192; U/M: EA; AEC Category: Q200
signal-integrity model Resistor
simulation model Resistor
footprint 0603
footprint 0603M
footprint 0603L
footprint 0603_HV
footprint 0603S
pins: 1, 2

## RT0603BRD0722R6L
designator R?  ValueDisplayed: 22.6  (hidden comment: RT0603BRD0722R6L)
RES, 22.6, 0.1%, 0.1 W, 0603; Manufacturer: Yageo America; CompType: Resistor; Value: 22.6; Value_Code: 22R6; Tolerance_%: 0.1; Value2: 0.1W; VDC_V: 75; TempCo: 25 ppm/C; SizeArea_mm2: 1.28; SizeX_mm: 1.6; SizeY_mm: 0.8; SizeZ_mm: 1; EIA_Code: E192; U/M: EA; AEC Category: Q200
signal-integrity model Resistor
simulation model Resistor
footprint 0603
footprint 0603M
footprint 0603L
footprint 0603_HV
footprint 0603S
pins: 1, 2

## RT0603BRD0722R9L
designator R?  ValueDisplayed: 22.9  (hidden comment: RT0603BRD0722R9L)
RES, 22.9, 0.1%, 0.1 W, 0603; Manufacturer: Yageo America; CompType: Resistor; Value: 22.9; Value_Code: 22R9; Tolerance_%: 0.1; Value2: 0.1W; VDC_V: 75; TempCo: 25 ppm/C; SizeArea_mm2: 1.28; SizeX_mm: 1.6; SizeY_mm: 0.8; SizeZ_mm: 1; EIA_Code: E192; U/M: EA; AEC Category: Q200
signal-integrity model Resistor
simulation model Resistor
footprint 0603
footprint 0603M
footprint 0603L
footprint 0603_HV
footprint 0603S
pins: 1, 2

## RT0603BRD0723K2L
designator R?  ValueDisplayed: 23.2k  (hidden comment: RT0603BRD0723K2L)
RES, 23.2 k, 0.1%, 0.1 W, 0603; Manufacturer: Yageo America; CompType: Resistor; Value: 23.2k; Res_ohm: 23200; Value_Code: 23k2; Tolerance_%: 0.1; Value2: 0.1W; VDC_V: 75; TempCo: 25 ppm/C; SizeArea_mm2: 1.28; SizeX_mm: 1.6; SizeY_mm: 0.8; SizeZ_mm: 1; EIA_Code: E192; U/M: EA; AEC Category: Q200
signal-integrity model Resistor
simulation model Resistor
footprint 0603
footprint 0603M
footprint 0603L
footprint 0603_HV
footprint 0603S
pins: 1, 2

## RT0603BRD0723K4L
designator R?  ValueDisplayed: 23.4k  (hidden comment: RT0603BRD0723K4L)
RES, 23.4 k, 0.1%, 0.1 W, 0603; Manufacturer: Yageo America; CompType: Resistor; Value: 23.4k; Res_ohm: 23400; Value_Code: 23k4; Tolerance_%: 0.1; Value2: 0.1W; VDC_V: 75; TempCo: 25 ppm/C; SizeArea_mm2: 1.28; SizeX_mm: 1.6; SizeY_mm: 0.8; SizeZ_mm: 1; EIA_Code: E192; U/M: EA; AEC Category: Q200
signal-integrity model Resistor
simulation model Resistor
footprint 0603
footprint 0603M
footprint 0603L
footprint 0603_HV
footprint 0603S
pins: 1, 2

## RT0603BRD0723K7L
designator R?  ValueDisplayed: 23.7k  (hidden comment: RT0603BRD0723K7L)
RES, 23.7 k, 0.1%, 0.1 W, 0603; Manufacturer: Yageo America; CompType: Resistor; Value: 23.7k; Res_ohm: 23700; Value_Code: 23k7; Tolerance_%: 0.1; Value2: 0.1W; VDC_V: 75; TempCo: 25 ppm/C; SizeArea_mm2: 1.28; SizeX_mm: 1.6; SizeY_mm: 0.8; SizeZ_mm: 1; EIA_Code: E192; U/M: EA; AEC Category: Q200
signal-integrity model Resistor
simulation model Resistor
footprint 0603
footprint 0603M
footprint 0603L
footprint 0603_HV
footprint 0603S
pins: 1, 2

## RT0603BRD0723R2L
designator R?  ValueDisplayed: 23.2  (hidden comment: RT0603BRD0723R2L)
RES, 23.2, 0.1%, 0.1 W, 0603; Manufacturer: Yageo America; CompType: Resistor; Value: 23.2; Value_Code: 23R2; Tolerance_%: 0.1; Value2: 0.1W; VDC_V: 75; TempCo: 25 ppm/C; SizeArea_mm2: 1.28; SizeX_mm: 1.6; SizeY_mm: 0.8; SizeZ_mm: 1; EIA_Code: E192; U/M: EA; AEC Category: Q200
signal-integrity model Resistor
simulation model Resistor
footprint 0603
footprint 0603M
footprint 0603L
footprint 0603_HV
footprint 0603S
pins: 1, 2

## RT0603BRD0723R4L
designator R?  ValueDisplayed: 23.4  (hidden comment: RT0603BRD0723R4L)
RES, 23.4, 0.1%, 0.1 W, 0603; Manufacturer: Yageo America; CompType: Resistor; Value: 23.4; Value_Code: 23R4; Tolerance_%: 0.1; Value2: 0.1W; VDC_V: 75; TempCo: 25 ppm/C; SizeArea_mm2: 1.28; SizeX_mm: 1.6; SizeY_mm: 0.8; SizeZ_mm: 1; EIA_Code: E192; U/M: EA; AEC Category: Q200
signal-integrity model Resistor
simulation model Resistor
footprint 0603
footprint 0603M
footprint 0603L
footprint 0603_HV
footprint 0603S
pins: 1, 2

## RT0603BRD0723R7L
designator R?  ValueDisplayed: 23.7  (hidden comment: RT0603BRD0723R7L)
RES, 23.7, 0.1%, 0.1 W, 0603; Manufacturer: Yageo America; CompType: Resistor; Value: 23.7; Value_Code: 23R7; Tolerance_%: 0.1; Value2: 0.1W; VDC_V: 75; TempCo: 25 ppm/C; SizeArea_mm2: 1.28; SizeX_mm: 1.6; SizeY_mm: 0.8; SizeZ_mm: 1; EIA_Code: E192; U/M: EA; AEC Category: Q200
signal-integrity model Resistor
simulation model Resistor
footprint 0603
footprint 0603M
footprint 0603L
footprint 0603_HV
footprint 0603S
pins: 1, 2

## RT0603BRD0724K3L
designator R?  ValueDisplayed: 24.3k  (hidden comment: RT0603BRD0724K3L)
RES, 24.3 k, 0.1%, 0.1 W, 0603; Manufacturer: Yageo America; CompType: Resistor; Value: 24.3k; Res_ohm: 24300; Value_Code: 24k3; Tolerance_%: 0.1; Value2: 0.1W; VDC_V: 75; TempCo: 25 ppm/C; SizeArea_mm2: 1.28; SizeX_mm: 1.6; SizeY_mm: 0.8; SizeZ_mm: 1; EIA_Code: E192; U/M: EA; AEC Category: Q200
signal-integrity model Resistor
simulation model Resistor
footprint 0603
footprint 0603M
footprint 0603L
footprint 0603_HV
footprint 0603S
pins: 1, 2

## RT0603BRD0724K6L
designator R?  ValueDisplayed: 24.6k  (hidden comment: RT0603BRD0724K6L)
RES, 24.6 k, 0.1%, 0.1 W, 0603; Manufacturer: Yageo America; CompType: Resistor; Value: 24.6k; Res_ohm: 24600; Value_Code: 24k6; Tolerance_%: 0.1; Value2: 0.1W; VDC_V: 75; TempCo: 25 ppm/C; SizeArea_mm2: 1.28; SizeX_mm: 1.6; SizeY_mm: 0.8; SizeZ_mm: 1; EIA_Code: E192; U/M: EA; AEC Category: Q200
signal-integrity model Resistor
simulation model Resistor
footprint 0603
footprint 0603M
footprint 0603L
footprint 0603_HV
footprint 0603S
pins: 1, 2

## RT0603BRD0724K9L
designator R?  ValueDisplayed: 24.9k  (hidden comment: RT0603BRD0724K9L)
RES, 24.9 k, 0.1%, 0.1 W, 0603; Manufacturer: Yageo America; CompType: Resistor; Value: 24.9k; Res_ohm: 24900; Value_Code: 24k9; Tolerance_%: 0.1; Value2: 0.1W; VDC_V: 75; TempCo: 25 ppm/C; SizeArea_mm2: 1.28; SizeX_mm: 1.6; SizeY_mm: 0.8; SizeZ_mm: 1; EIA_Code: E192; U/M: EA; AEC Category: Q200
signal-integrity model Resistor
simulation model Resistor
footprint 0603
footprint 0603M
footprint 0603L
footprint 0603_HV
footprint 0603S
pins: 1, 2

## RT0603BRD0724KL
designator R?  ValueDisplayed: 24.0k  (hidden comment: RT0603BRD0724KL)
RES, 24.0 k, 0.1%, 0.1 W, 0603; Manufacturer: Yageo America; CompType: Resistor; Value: 24.0k; Res_ohm: 24000; Value_Code: 24k0; Tolerance_%: 0.1; Value2: 0.1W; VDC_V: 75; TempCo: 25 ppm/C; SizeArea_mm2: 1.28; SizeX_mm: 1.6; SizeY_mm: 0.8; SizeZ_mm: 1; EIA_Code: E192; U/M: EA; AEC Category: Q200
signal-integrity model Resistor
simulation model Resistor
footprint 0603
footprint 0603M
footprint 0603L
footprint 0603_HV
footprint 0603S
pins: 1, 2

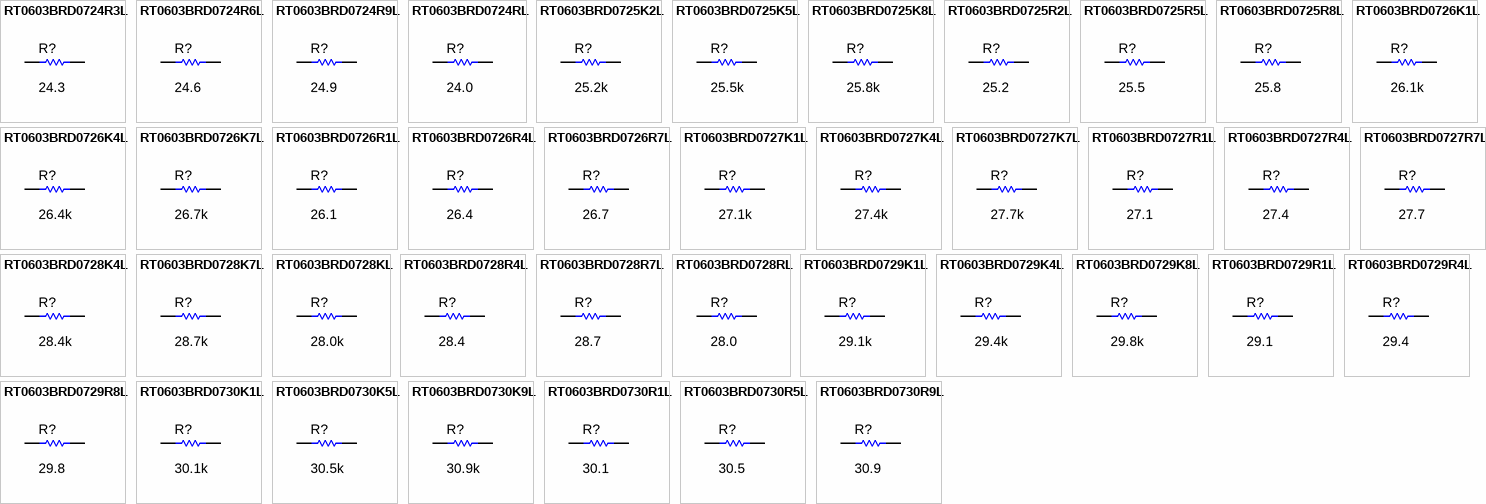
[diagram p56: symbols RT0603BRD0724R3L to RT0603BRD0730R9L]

## RT0603BRD0724R3L
designator R?  ValueDisplayed: 24.3  (hidden comment: RT0603BRD0724R3L)
RES, 24.3, 0.1%, 0.1 W, 0603; Manufacturer: Yageo America; CompType: Resistor; Value: 24.3; Value_Code: 24R3; Tolerance_%: 0.1; Value2: 0.1W; VDC_V: 75; TempCo: 25 ppm/C; SizeArea_mm2: 1.28; SizeX_mm: 1.6; SizeY_mm: 0.8; SizeZ_mm: 1; EIA_Code: E192; U/M: EA; AEC Category: Q200
signal-integrity model Resistor
simulation model Resistor
footprint 0603
footprint 0603M
footprint 0603L
footprint 0603_HV
footprint 0603S
pins: 1, 2

## RT0603BRD0724R6L
designator R?  ValueDisplayed: 24.6  (hidden comment: RT0603BRD0724R6L)
RES, 24.6, 0.1%, 0.1 W, 0603; Manufacturer: Yageo America; CompType: Resistor; Value: 24.6; Value_Code: 24R6; Tolerance_%: 0.1; Value2: 0.1W; VDC_V: 75; TempCo: 25 ppm/C; SizeArea_mm2: 1.28; SizeX_mm: 1.6; SizeY_mm: 0.8; SizeZ_mm: 1; EIA_Code: E192; U/M: EA; AEC Category: Q200
signal-integrity model Resistor
simulation model Resistor
footprint 0603
footprint 0603M
footprint 0603L
footprint 0603_HV
footprint 0603S
pins: 1, 2

## RT0603BRD0724R9L
designator R?  ValueDisplayed: 24.9  (hidden comment: RT0603BRD0724R9L)
RES, 24.9, 0.1%, 0.1 W, 0603; Manufacturer: Yageo America; CompType: Resistor; Value: 24.9; Value_Code: 24R9; Tolerance_%: 0.1; Value2: 0.1W; VDC_V: 75; TempCo: 25 ppm/C; SizeArea_mm2: 1.28; SizeX_mm: 1.6; SizeY_mm: 0.8; SizeZ_mm: 1; EIA_Code: E192; U/M: EA; AEC Category: Q200
signal-integrity model Resistor
simulation model Resistor
footprint 0603
footprint 0603M
footprint 0603L
footprint 0603_HV
footprint 0603S
pins: 1, 2

## RT0603BRD0724RL
designator R?  ValueDisplayed: 24.0  (hidden comment: RT0603BRD0724RL)
RES, 24.0, 0.1%, 0.1 W, 0603; Manufacturer: Yageo America; CompType: Resistor; Value: 24.0; Res_ohm: 24; Value_Code: 24R0; Tolerance_%: 0.1; Value2: 0.1W; VDC_V: 75; TempCo: 25 ppm/C; SizeArea_mm2: 1.28; SizeX_mm: 1.6; SizeY_mm: 0.8; SizeZ_mm: 1; EIA_Code: E192; U/M: EA; AEC Category: Q200
signal-integrity model Resistor
simulation model Resistor
footprint 0603
footprint 0603M
footprint 0603L
footprint 0603_HV
footprint 0603S
pins: 1, 2

## RT0603BRD0725K2L
designator R?  ValueDisplayed: 25.2k  (hidden comment: RT0603BRD0725K2L)
RES, 25.2 k, 0.1%, 0.1 W, 0603; Manufacturer: Yageo America; CompType: Resistor; Value: 25.2k; Res_ohm: 25200; Value_Code: 25k2; Tolerance_%: 0.1; Value2: 0.1W; VDC_V: 75; TempCo: 25 ppm/C; SizeArea_mm2: 1.28; SizeX_mm: 1.6; SizeY_mm: 0.8; SizeZ_mm: 1; EIA_Code: E192; U/M: EA; AEC Category: Q200
signal-integrity model Resistor
simulation model Resistor
footprint 0603
footprint 0603M
footprint 0603L
footprint 0603_HV
footprint 0603S
pins: 1, 2

## RT0603BRD0725K5L
designator R?  ValueDisplayed: 25.5k  (hidden comment: RT0603BRD0725K5L)
RES, 25.5 k, 0.1%, 0.1 W, 0603; Manufacturer: Yageo America; CompType: Resistor; Value: 25.5k; Res_ohm: 25500; Value_Code: 25k5; Tolerance_%: 0.1; Value2: 0.1W; VDC_V: 75; TempCo: 25 ppm/C; SizeArea_mm2: 1.28; SizeX_mm: 1.6; SizeY_mm: 0.8; SizeZ_mm: 1; EIA_Code: E192; U/M: EA; AEC Category: Q200
signal-integrity model Resistor
simulation model Resistor
footprint 0603
footprint 0603M
footprint 0603L
footprint 0603_HV
footprint 0603S
pins: 1, 2

## RT0603BRD0725K8L
designator R?  ValueDisplayed: 25.8k  (hidden comment: RT0603BRD0725K8L)
RES, 25.8 k, 0.1%, 0.1 W, 0603; Manufacturer: Yageo America; CompType: Resistor; Value: 25.8k; Res_ohm: 25800; Value_Code: 25k8; Tolerance_%: 0.1; Value2: 0.1W; VDC_V: 75; TempCo: 25 ppm/C; SizeArea_mm2: 1.28; SizeX_mm: 1.6; SizeY_mm: 0.8; SizeZ_mm: 1; EIA_Code: E192; U/M: EA; AEC Category: Q200
signal-integrity model Resistor
simulation model Resistor
footprint 0603
footprint 0603M
footprint 0603L
footprint 0603_HV
footprint 0603S
pins: 1, 2

## RT0603BRD0725R2L
designator R?  ValueDisplayed: 25.2  (hidden comment: RT0603BRD0725R2L)
RES, 25.2, 0.1%, 0.1 W, 0603; Manufacturer: Yageo America; CompType: Resistor; Value: 25.2; Value_Code: 25R2; Tolerance_%: 0.1; Value2: 0.1W; VDC_V: 75; TempCo: 25 ppm/C; SizeArea_mm2: 1.28; SizeX_mm: 1.6; SizeY_mm: 0.8; SizeZ_mm: 1; EIA_Code: E192; U/M: EA; AEC Category: Q200
signal-integrity model Resistor
simulation model Resistor
footprint 0603
footprint 0603M
footprint 0603L
footprint 0603_HV
footprint 0603S
pins: 1, 2

## RT0603BRD0725R5L
designator R?  ValueDisplayed: 25.5  (hidden comment: RT0603BRD0725R5L)
RES, 25.5, 0.1%, 0.1 W, 0603; Manufacturer: Yageo America; CompType: Resistor; Value: 25.5; Value_Code: 25R5; Tolerance_%: 0.1; Value2: 0.1W; VDC_V: 75; TempCo: 25 ppm/C; SizeArea_mm2: 1.28; SizeX_mm: 1.6; SizeY_mm: 0.8; SizeZ_mm: 1; EIA_Code: E192; U/M: EA; AEC Category: Q200
signal-integrity model Resistor
simulation model Resistor
footprint 0603
footprint 0603M
footprint 0603L
footprint 0603_HV
footprint 0603S
pins: 1, 2

## RT0603BRD0725R8L
designator R?  ValueDisplayed: 25.8  (hidden comment: RT0603BRD0725R8L)
RES, 25.8, 0.1%, 0.1 W, 0603; Manufacturer: Yageo America; CompType: Resistor; Value: 25.8; Value_Code: 25R8; Tolerance_%: 0.1; Value2: 0.1W; VDC_V: 75; TempCo: 25 ppm/C; SizeArea_mm2: 1.28; SizeX_mm: 1.6; SizeY_mm: 0.8; SizeZ_mm: 1; EIA_Code: E192; U/M: EA; AEC Category: Q200
signal-integrity model Resistor
simulation model Resistor
footprint 0603
footprint 0603M
footprint 0603L
footprint 0603_HV
footprint 0603S
pins: 1, 2

## RT0603BRD0726K1L
designator R?  ValueDisplayed: 26.1k  (hidden comment: RT0603BRD0726K1L)
RES, 26.1 k, 0.1%, 0.1 W, 0603; Manufacturer: Yageo America; CompType: Resistor; Value: 26.1k; Res_ohm: 26100; Value_Code: 26k1; Tolerance_%: 0.1; Value2: 0.1W; VDC_V: 75; TempCo: 25 ppm/C; SizeArea_mm2: 1.28; SizeX_mm: 1.6; SizeY_mm: 0.8; SizeZ_mm: 1; EIA_Code: E192; U/M: EA; AEC Category: Q200
signal-integrity model Resistor
simulation model Resistor
footprint 0603
footprint 0603M
footprint 0603L
footprint 0603_HV
footprint 0603S
pins: 1, 2

## RT0603BRD0726K4L
designator R?  ValueDisplayed: 26.4k  (hidden comment: RT0603BRD0726K4L)
RES, 26.4 k, 0.1%, 0.1 W, 0603; Manufacturer: Yageo America; CompType: Resistor; Value: 26.4k; Res_ohm: 26400; Value_Code: 26k4; Tolerance_%: 0.1; Value2: 0.1W; VDC_V: 75; TempCo: 25 ppm/C; SizeArea_mm2: 1.28; SizeX_mm: 1.6; SizeY_mm: 0.8; SizeZ_mm: 1; EIA_Code: E192; U/M: EA; AEC Category: Q200
signal-integrity model Resistor
simulation model Resistor
footprint 0603
footprint 0603M
footprint 0603L
footprint 0603_HV
footprint 0603S
pins: 1, 2

## RT0603BRD0726K7L
designator R?  ValueDisplayed: 26.7k  (hidden comment: RT0603BRD0726K7L)
RES, 26.7 k, 0.1%, 0.1 W, 0603; Manufacturer: Yageo America; CompType: Resistor; Value: 26.7k; Res_ohm: 26700; Value_Code: 26k7; Tolerance_%: 0.1; Value2: 0.1W; VDC_V: 75; TempCo: 25 ppm/C; SizeArea_mm2: 1.28; SizeX_mm: 1.6; SizeY_mm: 0.8; SizeZ_mm: 1; EIA_Code: E192; U/M: EA; AEC Category: Q200
signal-integrity model Resistor
simulation model Resistor
footprint 0603
footprint 0603M
footprint 0603L
footprint 0603_HV
footprint 0603S
pins: 1, 2

## RT0603BRD0726R1L
designator R?  ValueDisplayed: 26.1  (hidden comment: RT0603BRD0726R1L)
RES, 26.1, 0.1%, 0.1 W, 0603; Manufacturer: Yageo America; CompType: Resistor; Value: 26.1; Value_Code: 26R1; Tolerance_%: 0.1; Value2: 0.1W; VDC_V: 75; TempCo: 25 ppm/C; SizeArea_mm2: 1.28; SizeX_mm: 1.6; SizeY_mm: 0.8; SizeZ_mm: 1; EIA_Code: E192; U/M: EA; AEC Category: Q200
signal-integrity model Resistor
simulation model Resistor
footprint 0603
footprint 0603M
footprint 0603L
footprint 0603_HV
footprint 0603S
pins: 1, 2

## RT0603BRD0726R4L
designator R?  ValueDisplayed: 26.4  (hidden comment: RT0603BRD0726R4L)
RES, 26.4, 0.1%, 0.1 W, 0603; Manufacturer: Yageo America; CompType: Resistor; Value: 26.4; Value_Code: 26R4; Tolerance_%: 0.1; Value2: 0.1W; VDC_V: 75; TempCo: 25 ppm/C; SizeArea_mm2: 1.28; SizeX_mm: 1.6; SizeY_mm: 0.8; SizeZ_mm: 1; EIA_Code: E192; U/M: EA; AEC Category: Q200
signal-integrity model Resistor
simulation model Resistor
footprint 0603
footprint 0603M
footprint 0603L
footprint 0603_HV
footprint 0603S
pins: 1, 2

## RT0603BRD0726R7L
designator R?  ValueDisplayed: 26.7  (hidden comment: RT0603BRD0726R7L)
RES, 26.7, 0.1%, 0.1 W, 0603; Manufacturer: Yageo America; CompType: Resistor; Value: 26.7; Value_Code: 26R7; Tolerance_%: 0.1; Value2: 0.1W; VDC_V: 75; TempCo: 25 ppm/C; SizeArea_mm2: 1.28; SizeX_mm: 1.6; SizeY_mm: 0.8; SizeZ_mm: 1; EIA_Code: E192; U/M: EA; AEC Category: Q200
signal-integrity model Resistor
simulation model Resistor
footprint 0603
footprint 0603M
footprint 0603L
footprint 0603_HV
footprint 0603S
pins: 1, 2

## RT0603BRD0727K1L
designator R?  ValueDisplayed: 27.1k  (hidden comment: RT0603BRD0727K1L)
RES, 27.1 k, 0.1%, 0.1 W, 0603; Manufacturer: Yageo America; CompType: Resistor; Value: 27.1k; Res_ohm: 27100; Value_Code: 27k1; Tolerance_%: 0.1; Value2: 0.1W; VDC_V: 75; TempCo: 25 ppm/C; SizeArea_mm2: 1.28; SizeX_mm: 1.6; SizeY_mm: 0.8; SizeZ_mm: 1; EIA_Code: E192; U/M: EA; AEC Category: Q200
signal-integrity model Resistor
simulation model Resistor
footprint 0603
footprint 0603M
footprint 0603L
footprint 0603_HV
footprint 0603S
pins: 1, 2

## RT0603BRD0727K4L
designator R?  ValueDisplayed: 27.4k  (hidden comment: RT0603BRD0727K4L)
RES, 27.4 k, 0.1%, 0.1 W, 0603; Manufacturer: Yageo America; CompType: Resistor; Value: 27.4k; Res_ohm: 27400; Value_Code: 27k4; Tolerance_%: 0.1; Value2: 0.1W; VDC_V: 75; TempCo: 25 ppm/C; SizeArea_mm2: 1.28; SizeX_mm: 1.6; SizeY_mm: 0.8; SizeZ_mm: 1; EIA_Code: E192; U/M: EA; AEC Category: Q200
signal-integrity model Resistor
simulation model Resistor
footprint 0603
footprint 0603M
footprint 0603L
footprint 0603_HV
footprint 0603S
pins: 1, 2

## RT0603BRD0727K7L
designator R?  ValueDisplayed: 27.7k  (hidden comment: RT0603BRD0727K7L)
RES, 27.7 k, 0.1%, 0.1 W, 0603; Manufacturer: Yageo America; CompType: Resistor; Value: 27.7k; Res_ohm: 27700; Value_Code: 27k7; Tolerance_%: 0.1; Value2: 0.1W; VDC_V: 75; TempCo: 25 ppm/C; SizeArea_mm2: 1.28; SizeX_mm: 1.6; SizeY_mm: 0.8; SizeZ_mm: 1; EIA_Code: E192; U/M: EA; AEC Category: Q200
signal-integrity model Resistor
simulation model Resistor
footprint 0603
footprint 0603M
footprint 0603L
footprint 0603_HV
footprint 0603S
pins: 1, 2

## RT0603BRD0727R1L
designator R?  ValueDisplayed: 27.1  (hidden comment: RT0603BRD0727R1L)
RES, 27.1, 0.1%, 0.1 W, 0603; Manufacturer: Yageo America; CompType: Resistor; Value: 27.1; Value_Code: 27R1; Tolerance_%: 0.1; Value2: 0.1W; VDC_V: 75; TempCo: 25 ppm/C; SizeArea_mm2: 1.28; SizeX_mm: 1.6; SizeY_mm: 0.8; SizeZ_mm: 1; EIA_Code: E192; U/M: EA; AEC Category: Q200
signal-integrity model Resistor
simulation model Resistor
footprint 0603
footprint 0603M
footprint 0603L
footprint 0603_HV
footprint 0603S
pins: 1, 2

## RT0603BRD0727R4L
designator R?  ValueDisplayed: 27.4  (hidden comment: RT0603BRD0727R4L)
RES, 27.4, 0.1%, 0.1 W, 0603; Manufacturer: Yageo America; CompType: Resistor; Value: 27.4; Value_Code: 27R4; Tolerance_%: 0.1; Value2: 0.1W; VDC_V: 75; TempCo: 25 ppm/C; SizeArea_mm2: 1.28; SizeX_mm: 1.6; SizeY_mm: 0.8; SizeZ_mm: 1; EIA_Code: E192; U/M: EA; AEC Category: Q200
signal-integrity model Resistor
simulation model Resistor
footprint 0603
footprint 0603M
footprint 0603L
footprint 0603_HV
footprint 0603S
pins: 1, 2

## RT0603BRD0727R7L
designator R?  ValueDisplayed: 27.7  (hidden comment: RT0603BRD0727R7L)
RES, 27.7, 0.1%, 0.1 W, 0603; Manufacturer: Yageo America; CompType: Resistor; Value: 27.7; Value_Code: 27R7; Tolerance_%: 0.1; Value2: 0.1W; VDC_V: 75; TempCo: 25 ppm/C; SizeArea_mm2: 1.28; SizeX_mm: 1.6; SizeY_mm: 0.8; SizeZ_mm: 1; EIA_Code: E192; U/M: EA; AEC Category: Q200
signal-integrity model Resistor
simulation model Resistor
footprint 0603
footprint 0603M
footprint 0603L
footprint 0603_HV
footprint 0603S
pins: 1, 2

## RT0603BRD0728K4L
designator R?  ValueDisplayed: 28.4k  (hidden comment: RT0603BRD0728K4L)
RES, 28.4 k, 0.1%, 0.1 W, 0603; Manufacturer: Yageo America; CompType: Resistor; Value: 28.4k; Res_ohm: 28400; Value_Code: 28k4; Tolerance_%: 0.1; Value2: 0.1W; VDC_V: 75; TempCo: 25 ppm/C; SizeArea_mm2: 1.28; SizeX_mm: 1.6; SizeY_mm: 0.8; SizeZ_mm: 1; EIA_Code: E192; U/M: EA; AEC Category: Q200
signal-integrity model Resistor
simulation model Resistor
footprint 0603
footprint 0603M
footprint 0603L
footprint 0603_HV
footprint 0603S
pins: 1, 2

## RT0603BRD0728K7L
designator R?  ValueDisplayed: 28.7k  (hidden comment: RT0603BRD0728K7L)
RES, 28.7 k, 0.1%, 0.1 W, 0603; Manufacturer: Yageo America; CompType: Resistor; Value: 28.7k; Res_ohm: 28700; Value_Code: 28k7; Tolerance_%: 0.1; Value2: 0.1W; VDC_V: 75; TempCo: 25 ppm/C; SizeArea_mm2: 1.28; SizeX_mm: 1.6; SizeY_mm: 0.8; SizeZ_mm: 1; EIA_Code: E192; U/M: EA; AEC Category: Q200
signal-integrity model Resistor
simulation model Resistor
footprint 0603
footprint 0603M
footprint 0603L
footprint 0603_HV
footprint 0603S
pins: 1, 2

## RT0603BRD0728KL
designator R?  ValueDisplayed: 28.0k  (hidden comment: RT0603BRD0728KL)
RES, 28.0 k, 0.1%, 0.1 W, 0603; Manufacturer: Yageo America; CompType: Resistor; Value: 28.0k; Res_ohm: 28000; Value_Code: 28k0; Tolerance_%: 0.1; Value2: 0.1W; VDC_V: 75; TempCo: 25 ppm/C; SizeArea_mm2: 1.28; SizeX_mm: 1.6; SizeY_mm: 0.8; SizeZ_mm: 1; EIA_Code: E192; U/M: EA; AEC Category: Q200
signal-integrity model Resistor
simulation model Resistor
footprint 0603
footprint 0603M
footprint 0603L
footprint 0603_HV
footprint 0603S
pins: 1, 2

## RT0603BRD0728R4L
designator R?  ValueDisplayed: 28.4  (hidden comment: RT0603BRD0728R4L)
RES, 28.4, 0.1%, 0.1 W, 0603; Manufacturer: Yageo America; CompType: Resistor; Value: 28.4; Value_Code: 28R4; Tolerance_%: 0.1; Value2: 0.1W; VDC_V: 75; TempCo: 25 ppm/C; SizeArea_mm2: 1.28; SizeX_mm: 1.6; SizeY_mm: 0.8; SizeZ_mm: 1; EIA_Code: E192; U/M: EA; AEC Category: Q200
signal-integrity model Resistor
simulation model Resistor
footprint 0603
footprint 0603M
footprint 0603L
footprint 0603_HV
footprint 0603S
pins: 1, 2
